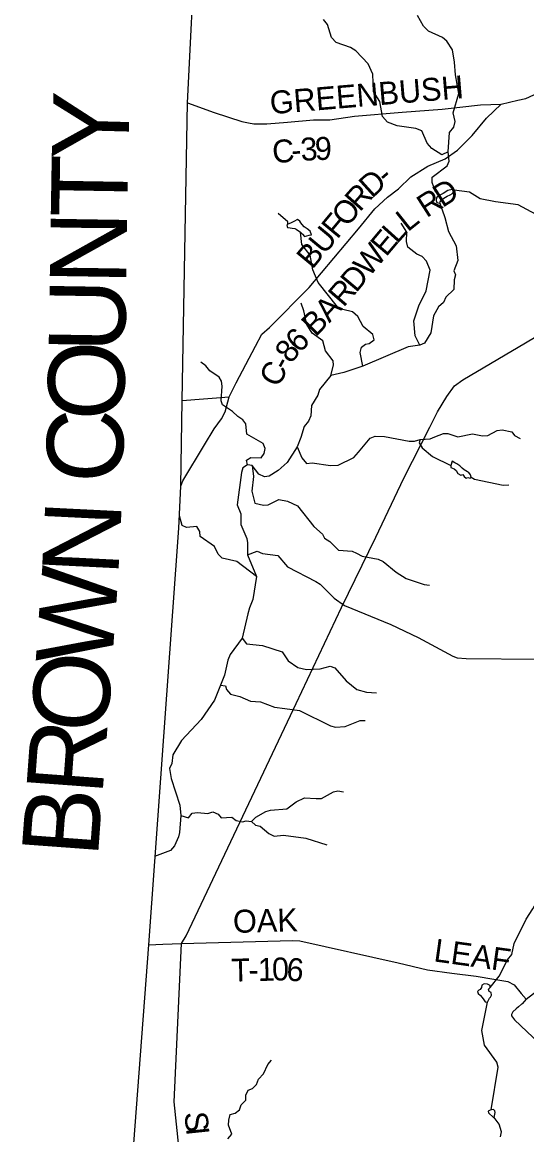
# Model space of a CAD drawing. Extents: x 1525783 to 1900577, y 218250 to 627376.
# Drawn here: x 1577543 to 1584144, y 379295 to 393837 of the extents above; entities that cross this region are included whole.
import ezdxf

# ---------------------------------------------------------------- set-up
doc = ezdxf.new("R2010")
doc.units = 0
for name, color, linetype in [('GM_X_Adjacent_County', 7, 'Continuous'), ('GM_X_Adjacent_County_Text', 7, 'Continuous'), ('GM_X_County', 7, 'Continuous'), ('GM_X_County_Road', 7, 'Continuous'), ('GM_X_County_Road_Text', 7, 'Continuous'), ('GM_X_Minor_Lake', 7, 'Continuous'), ('GM_X_Minor_River', 7, 'Continuous'), ('GM_X_Township', 7, 'Continuous'), ('GM_X_Township_Road', 7, 'Continuous'), ('GM_X_Township_Road_Text', 7, 'Continuous')]:
    doc.layers.add(name, color=color, linetype=linetype)

msp = doc.modelspace()

# ---------------------------------------------------------------- linework, layer by layer
at = {"layer": 'GM_X_Adjacent_County'}
msp.add_lwpolyline([(1613116, 374096), (1606320, 374160), (1604029, 374172), (1603265, 374179), (1596599, 374241), (1594394, 374306), (1593734, 374365), (1593113, 374425), (1589266, 374523), (1588677, 374545), (1587643, 374584), (1581292, 374793), (1580571, 374820), (1580347, 374828), (1578669, 374917), (1578743, 375741), (1578750, 375835), (1579198, 381778), (1579591, 387224), (1579618, 387771), (1579637, 388893), (1579705, 392782), (1579924, 397127)], dxfattribs=at)
at = {"layer": 'GM_X_County'}
msp.add_lwpolyline([(1613116, 374096), (1606320, 374160), (1604029, 374172), (1603265, 374179), (1596599, 374241), (1594394, 374306), (1593734, 374365), (1593113, 374425), (1589266, 374523), (1588677, 374545), (1587643, 374584), (1581292, 374793), (1580571, 374820), (1580347, 374828), (1578669, 374917), (1578743, 375741), (1578750, 375835), (1579198, 381778), (1579591, 387224), (1579618, 387771), (1579637, 388893), (1579705, 392782), (1579924, 397127)], dxfattribs=at)
at = {"layer": 'GM_X_County_Road'}
for points in [[(1579705, 392782), (1580053, 392656), (1580416, 392540), (1580504, 392522), (1580575, 392507), (1580742, 392507), (1581015, 392530), (1581353, 392560), (1581566, 392561), (1581888, 392610), (1582515, 392663), (1583036, 392701), (1583537, 392757), (1583809, 392768), (1584027, 392820), (1584133, 392840), (1584238, 392890), (1584374, 392972), (1584658, 393183), (1585194, 393709), (1585804, 394305), (1586176, 394518), (1586854, 394984)], [(1579691, 378181), (1579529, 379725), (1579625, 381794), (1579689, 381894), (1581051, 384777), (1581718, 386187), (1582167, 387107), (1582537, 387876), (1582874, 388545), (1582975, 388745), (1583099, 388947), (1583197, 389083), (1583309, 389163), (1584126, 389645), (1585202, 390282), (1585209, 390339), (1585221, 390472), (1585268, 393206), (1585242, 393451), (1585188, 393657), (1585194, 393709)], [(1579618, 387771), (1579644, 387841), (1579929, 388314), (1580052, 388524), (1580149, 388652), (1580196, 388745), (1580251, 388940), (1580344, 389122), (1580595, 389604), (1580679, 389760), (1580777, 389848), (1581299, 390369), (1581941, 391136), (1582155, 391398), (1582320, 391551), (1582464, 391658), (1582629, 391815), (1582848, 391956), (1583078, 392050), (1583237, 392165), (1583430, 392356), (1583616, 392582), (1583809, 392768)]]:
    msp.add_lwpolyline(points, dxfattribs=at)
at = {"layer": 'GM_X_Minor_Lake'}
for points in [[(1583006, 391474), (1583010, 391490), (1583028, 391516), (1583059, 391539), (1583103, 391565), (1583142, 391582), (1583170, 391599), (1583190, 391621), (1583195, 391641), (1583169, 391651), (1583111, 391638), (1583048, 391600), (1582997, 391572), (1582961, 391543), (1582958, 391507), (1582968, 391483)], [(1582968, 391483), (1583006, 391474)], [(1581185, 391092), (1581211, 391068), (1581235, 391035), (1581295, 391052), (1581327, 391060), (1581308, 391108), (1581272, 391135), (1581233, 391161), (1581205, 391192), (1581189, 391214), (1581174, 391236), (1581144, 391259), (1581096, 391233), (1581051, 391212), (1581019, 391199), (1581007, 391183), (1581014, 391155), (1581050, 391148), (1581076, 391146), (1581110, 391141), (1581128, 391133)], [(1581128, 391133), (1581185, 391092)], [(1583152, 388015), (1583193, 387999), (1583219, 387976), (1583243, 387938), (1583280, 387917), (1583306, 387925), (1583324, 387899), (1583350, 387878), (1583372, 387886), (1583402, 387879), (1583418, 387889), (1583408, 387919), (1583387, 387951), (1583369, 387962), (1583325, 387986), (1583298, 388009), (1583270, 388037), (1583229, 388064), (1583201, 388079), (1583169, 388099), (1583152, 388041)], [(1583152, 388041), (1583152, 388015)], [(1583656, 381079), (1583671, 381095), (1583681, 381120), (1583678, 381153), (1583650, 381167), (1583642, 381197), (1583663, 381221), (1583665, 381245), (1583632, 381265), (1583588, 381266), (1583557, 381251), (1583553, 381219), (1583536, 381195), (1583516, 381185), (1583498, 381168), (1583509, 381141), (1583537, 381115), (1583561, 381091), (1583580, 381060), (1583598, 381034), (1583628, 381027)], [(1583628, 381027), (1583656, 381079)], [(1583718, 379520), (1583731, 379586), (1583724, 379610), (1583708, 379626), (1583680, 379619), (1583655, 379611), (1583637, 379603), (1583643, 379581)], [(1583643, 379581), (1583708, 379520), (1583718, 379520)]]:
    msp.add_lwpolyline(points, dxfattribs=at)
at = {"layer": 'GM_X_Minor_River'}
for points in [[(1583115, 392142), (1583034, 392103), (1582903, 392186), (1582840, 392255), (1582773, 392418), (1582693, 392449), (1582447, 392481), (1582320, 392529), (1582255, 392605), (1582222, 392801), (1582140, 392930), (1582128, 393157), (1582070, 393295), (1581908, 393464), (1581839, 393509), (1581650, 393573), (1581591, 393638), (1581535, 393809), (1581486, 393871)], [(1582997, 391572), (1582948, 391619), (1582908, 391742), (1582907, 391814), (1583102, 391962), (1583129, 392020), (1583115, 392142), (1583131, 392398), (1583188, 392465), (1583207, 392538), (1583179, 392651), (1583257, 392905), (1583211, 393150), (1583200, 393314), (1583172, 393477), (1583098, 393590), (1583041, 393639), (1582860, 393722), (1582793, 393787), (1582715, 393924)], [(1584382, 391261), (1584033, 391449), (1583733, 391490), (1583533, 391529), (1583395, 391614), (1583195, 391641)], [(1583006, 391474), (1583073, 391285), (1583120, 391101), (1583221, 390915), (1583242, 390721), (1583190, 390586), (1583213, 390536), (1583192, 390472), (1583190, 390342), (1583085, 390242), (1583053, 390175), (1582988, 390116), (1582925, 389999), (1582887, 389778), (1582807, 389640), (1582746, 389617), (1582592, 389594), (1582001, 389340), (1581751, 389257), (1581581, 389220), (1581434, 389036), (1581410, 388963), (1581328, 388828), (1581318, 388693), (1581289, 388623), (1581230, 388554), (1581186, 388409), (1581140, 388288), (1581008, 388081), (1580892, 387977), (1580775, 387905), (1580711, 387894), (1580639, 387931), (1580551, 388045), (1580489, 388054), (1580428, 388011), (1580410, 387953), (1580353, 387531), (1580401, 387412), (1580405, 387270), (1580480, 387091), (1580489, 387031), (1580491, 386877), (1580606, 386591), (1580561, 386290), (1580515, 386181), (1580496, 386105), (1580419, 385784), (1580263, 385573), (1580232, 385500), (1580191, 385302), (1580137, 385173), (1580059, 384974), (1579883, 384721), (1579628, 384448), (1579515, 384260), (1579499, 384146), (1579468, 384084), (1579492, 383954), (1579606, 383602), (1579620, 383467), (1579602, 383247), (1579589, 383188), (1579537, 383070), (1579482, 383011), (1579274, 382932)], [(1581019, 391199), (1581017, 391229), (1580891, 391337)], [(1582746, 389617), (1582682, 389738), (1582665, 389936), (1582732, 390128), (1582829, 390325), (1582880, 390597), (1582832, 390714), (1582774, 390775), (1582707, 390806), (1582588, 390898), (1582571, 390970), (1582573, 391094), (1582501, 391211)], [(1582001, 389340), (1581964, 389520), (1581981, 389592), (1582034, 389631), (1582084, 389636), (1582149, 389685), (1582130, 389755), (1582003, 389859), (1581935, 389990), (1581862, 390052), (1581736, 390084), (1581667, 390119), (1581415, 390433), (1581344, 390600), (1581309, 390792), (1581201, 390930), (1581185, 391092)], [(1581581, 389220), (1581615, 389355), (1581612, 389413), (1581512, 389542), (1581476, 389673), (1581337, 389773), (1581267, 389886), (1581227, 390065), (1581191, 390167)], [(1580489, 388054), (1580478, 388114), (1580535, 388149), (1580667, 388145), (1580710, 388202), (1580721, 388266), (1580696, 388330), (1580483, 388453), (1580469, 388586), (1580428, 388642), (1580363, 388685), (1580296, 388750), (1580165, 388835), (1580144, 388887), (1580159, 389082), (1580148, 389144), (1580119, 389197), (1579998, 389281), (1579945, 389348), (1579881, 389395)], [(1581140, 388288), (1581199, 388143), (1581260, 388068), (1581337, 388079), (1581574, 388043), (1581677, 388049), (1581882, 388148), (1581941, 388216), (1582097, 388402), (1582159, 388428), (1582283, 388424), (1582605, 388363), (1582673, 388360), (1582749, 388382), (1582881, 388392), (1582940, 388419), (1583053, 388463), (1583111, 388460), (1583240, 388420), (1583435, 388458), (1583565, 388430), (1583635, 388437), (1583756, 388500), (1583824, 388511), (1583948, 388485), (1583985, 388435), (1584059, 388397)], [(1582749, 388382), (1582734, 388340), (1582775, 388272), (1582910, 388162), (1583152, 388041)], [(1580551, 388045), (1580569, 387901), (1580546, 387709), (1580585, 387549), (1580699, 387525), (1580761, 387530), (1580898, 387597), (1581012, 387575), (1581143, 387515), (1581360, 387247), (1581470, 387144), (1581499, 387093), (1581567, 387050), (1581679, 386936), (1581859, 386925), (1581917, 386896), (1581990, 386859), (1582198, 386819), (1582267, 386788), (1582435, 386649), (1582568, 386567), (1582801, 386487), (1582871, 386477)], [(1583418, 387889), (1583458, 387864), (1583837, 387788), (1583907, 387792)], [(1580606, 386591), (1580351, 386787), (1580157, 386831), (1580108, 386883), (1580060, 386984), (1579870, 387113), (1579867, 387179), (1579828, 387244), (1579693, 387234), (1579634, 387259), (1579599, 387384)], [(1580491, 386877), (1580617, 386924), (1580685, 386891), (1580887, 386866), (1581013, 386718), (1581384, 386525), (1581440, 386490), (1581623, 386307), (1581759, 386215), (1582364, 385964), (1582722, 385794), (1583176, 385552), (1583234, 385531), (1583350, 385521), (1584271, 385513), (1584333, 385510), (1584525, 385511), (1584554, 385582), (1584562, 385812), (1584585, 385879), (1584933, 385869), (1584995, 385868)], [(1580419, 385784), (1580478, 385713), (1580686, 385690), (1580943, 385609), (1581023, 385488), (1581148, 385404), (1581263, 385378), (1581442, 385385), (1581570, 385420), (1581634, 385397), (1581783, 385227), (1581920, 385116), (1582045, 385080), (1582179, 385072)], [(1580137, 385173), (1580201, 385164), (1580214, 385114), (1580267, 385055), (1580391, 385023), (1580530, 384962), (1580662, 384952), (1580843, 384883), (1580977, 384867), (1581172, 384839), (1581574, 384642), (1581643, 384625), (1581770, 384633), (1581965, 384711), (1582031, 384708)], [(1583663, 381221), (1583781, 381367), (1583893, 381583), (1583949, 381652), (1583977, 381794), (1584134, 382114), (1584223, 382248), (1584543, 382821), (1584560, 382903), (1584523, 383196), (1584431, 383914)], [(1580544, 383389), (1580601, 383448), (1580728, 383520), (1580792, 383539), (1581005, 383555), (1581129, 383649), (1581236, 383699), (1581388, 383691), (1581458, 383692), (1581615, 383777), (1581670, 383792), (1581746, 383779)], [(1579620, 383467), (1579717, 383438), (1579768, 383497), (1579835, 383506), (1579973, 383493), (1580037, 383514), (1580107, 383487), (1580144, 383436), (1580284, 383448), (1580344, 383403), (1580423, 383385), (1580474, 383400), (1580544, 383389), (1580597, 383340), (1580655, 383327), (1580771, 383231), (1580839, 383200), (1580961, 383210), (1581255, 383171), (1581530, 383086)], [(1583680, 379619), (1583769, 380178), (1583750, 380242), (1583590, 380465), (1583557, 380656), (1583570, 380722), (1583628, 381027)], [(1580232, 379244), (1580287, 379303), (1580240, 379422), (1580247, 379484), (1580262, 379558), (1580331, 379577), (1580385, 379622), (1580408, 379686), (1580467, 379749), (1580470, 379811), (1580501, 379879), (1580554, 379900), (1580608, 379950), (1580635, 380023), (1580701, 380090), (1580758, 380212), (1580805, 380271)], [(1583800, 379266), (1583813, 379334), (1583781, 379434), (1583718, 379520)]]:
    msp.add_lwpolyline(points, dxfattribs=at)
at = {"layer": 'GM_X_Township'}
msp.add_lwpolyline([(1604445, 398538), (1603468, 390634), (1602513, 389039), (1601754, 387770), (1596289, 378635), (1595319, 377014), (1593734, 374365), (1593113, 374425), (1589266, 374523), (1588677, 374545), (1587643, 374584), (1581292, 374793), (1580571, 374820), (1580347, 374828), (1578669, 374917), (1578743, 375741), (1578750, 375835), (1579198, 381778), (1579591, 387224), (1579618, 387771), (1579637, 388893), (1579705, 392782), (1579924, 397127)], dxfattribs=at)
at = {"layer": 'GM_X_Township_Road'}
for points in [[(1579637, 388893), (1580251, 388940)], [(1584135, 381066), (1585468, 382096), (1587204, 383431), (1588749, 384607)], [(1579198, 381778), (1579381, 381787), (1579625, 381794), (1581077, 381836), (1581173, 381829), (1582461, 381541), (1582844, 381451), (1583162, 381407), (1583482, 381370), (1583714, 381331), (1583898, 381300), (1583978, 381254), (1584070, 381142), (1584135, 381066), (1584083, 381008)], [(1584083, 381008), (1584075, 381000), (1584036, 380968), (1584004, 380943), (1583963, 380902), (1583945, 380868), (1583942, 380848), (1583982, 380799), (1584948, 379888), (1585796, 379073), (1586890, 378028), (1587347, 377600), (1588645, 376387), (1588961, 376237), (1589980, 375843), (1591089, 375567), (1591432, 375474), (1591599, 375401), (1592906, 374553), (1593113, 374425)]]:
    msp.add_lwpolyline(points, dxfattribs=at)

# ---------------------------------------------------------------- texts
at = {"layer": 'GM_X_Adjacent_County_Text'}
for s, rotation, p in [('Y', 88.4497, (1578928, 392025)), ('T', 89.0524, (1578916, 391280)), ('N', 89.0928, (1578902, 390396)), ('U', 89.093, (1578888, 389512)), ('O', 89.0809, (1578874, 388627)), ('C', 88.694, (1578855, 387806)), ('N', 87.1671, (1578799, 386590)), ('W', 86.0005, (1578717, 385418)), ('O', 85.7953, (1578652, 384532)), ('R', 85.7953, (1578592, 383721)), ('B', 85.7956, (1578532, 382909))]:
    msp.add_text(s, height=1000, rotation=rotation, dxfattribs=at).set_placement(p)
at = {"layer": 'GM_X_County_Road_Text'}
for s, rotation, p in [('GREENBUSH', 4.7824, (1580795, 392634)), ('3', 3.7756, (1581193, 392023)), ('9', 1.2959, (1581374, 392035)), ('C', 4.8102, (1580826, 391992)), ('-', 4.5713, (1581072, 392013)), ('D', 42.2486, (1582118, 391526)), ('-', 40.4167, (1582312, 391702)), ('D', 32.4831, (1583040, 391407)), ('R', 48.2846, (1581960, 391348)), ('R', 32.6362, (1582832, 391274)), ('O', 50.2628, (1581793, 391147)), ('F', 50.3373, (1581664, 390991)), ('L', 38.5507, (1582586, 391089)), ('U', 50.3364, (1581496, 390788)), ('L', 48.069, (1582446, 390931)), ('E', 49.9373, (1582303, 390761)), ('B', 50.3376, (1581338, 390598)), ('W', 50.1663, (1582080, 390494)), ('D', 50.1068, (1581911, 390291)), ('R', 49.2892, (1581747, 390101)), ('A', 47.5312, (1581562, 389899)), ('B', 45.296, (1581380, 389715)), ('6', 44.9025, (1581167, 389502)), ('8', 51.8561, (1581059, 389363)), ('-', 61.443, (1581007, 389266)), ('C', 62.0664, (1580892, 389049)), ('S', 275.9621, (1579663, 379583)), ('I', 275.9611, (1579685, 379382))]:
    msp.add_text(s, height=300, rotation=rotation, dxfattribs=at).set_placement(p)
at = {"layer": 'GM_X_Township_Road_Text'}
for s, rotation, p in [('OAK', 1.5776, (1580304, 381933)), ('LEAF', 352.0134, (1582917, 381563)), ('T', 1.5559, (1580282, 381295)), ('1', 1.5197, (1580629, 381304)), ('0', 1.3948, (1580814, 381309)), ('6', 354.8828, (1580990, 381314)), ('-', 1.5458, (1580506, 381301))]:
    msp.add_text(s, height=300, rotation=rotation, dxfattribs=at).set_placement(p)

doc.saveas('drawing.dxf')
